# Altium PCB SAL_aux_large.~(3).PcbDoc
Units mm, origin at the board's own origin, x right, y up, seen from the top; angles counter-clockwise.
Board outline 62 x 80 mm, 2 copper layers (Top Layer, Bottom Layer); 29 components, 48 nets, 142 pads, 0 vias.
Unrouted connection lines stored in the file: 78.
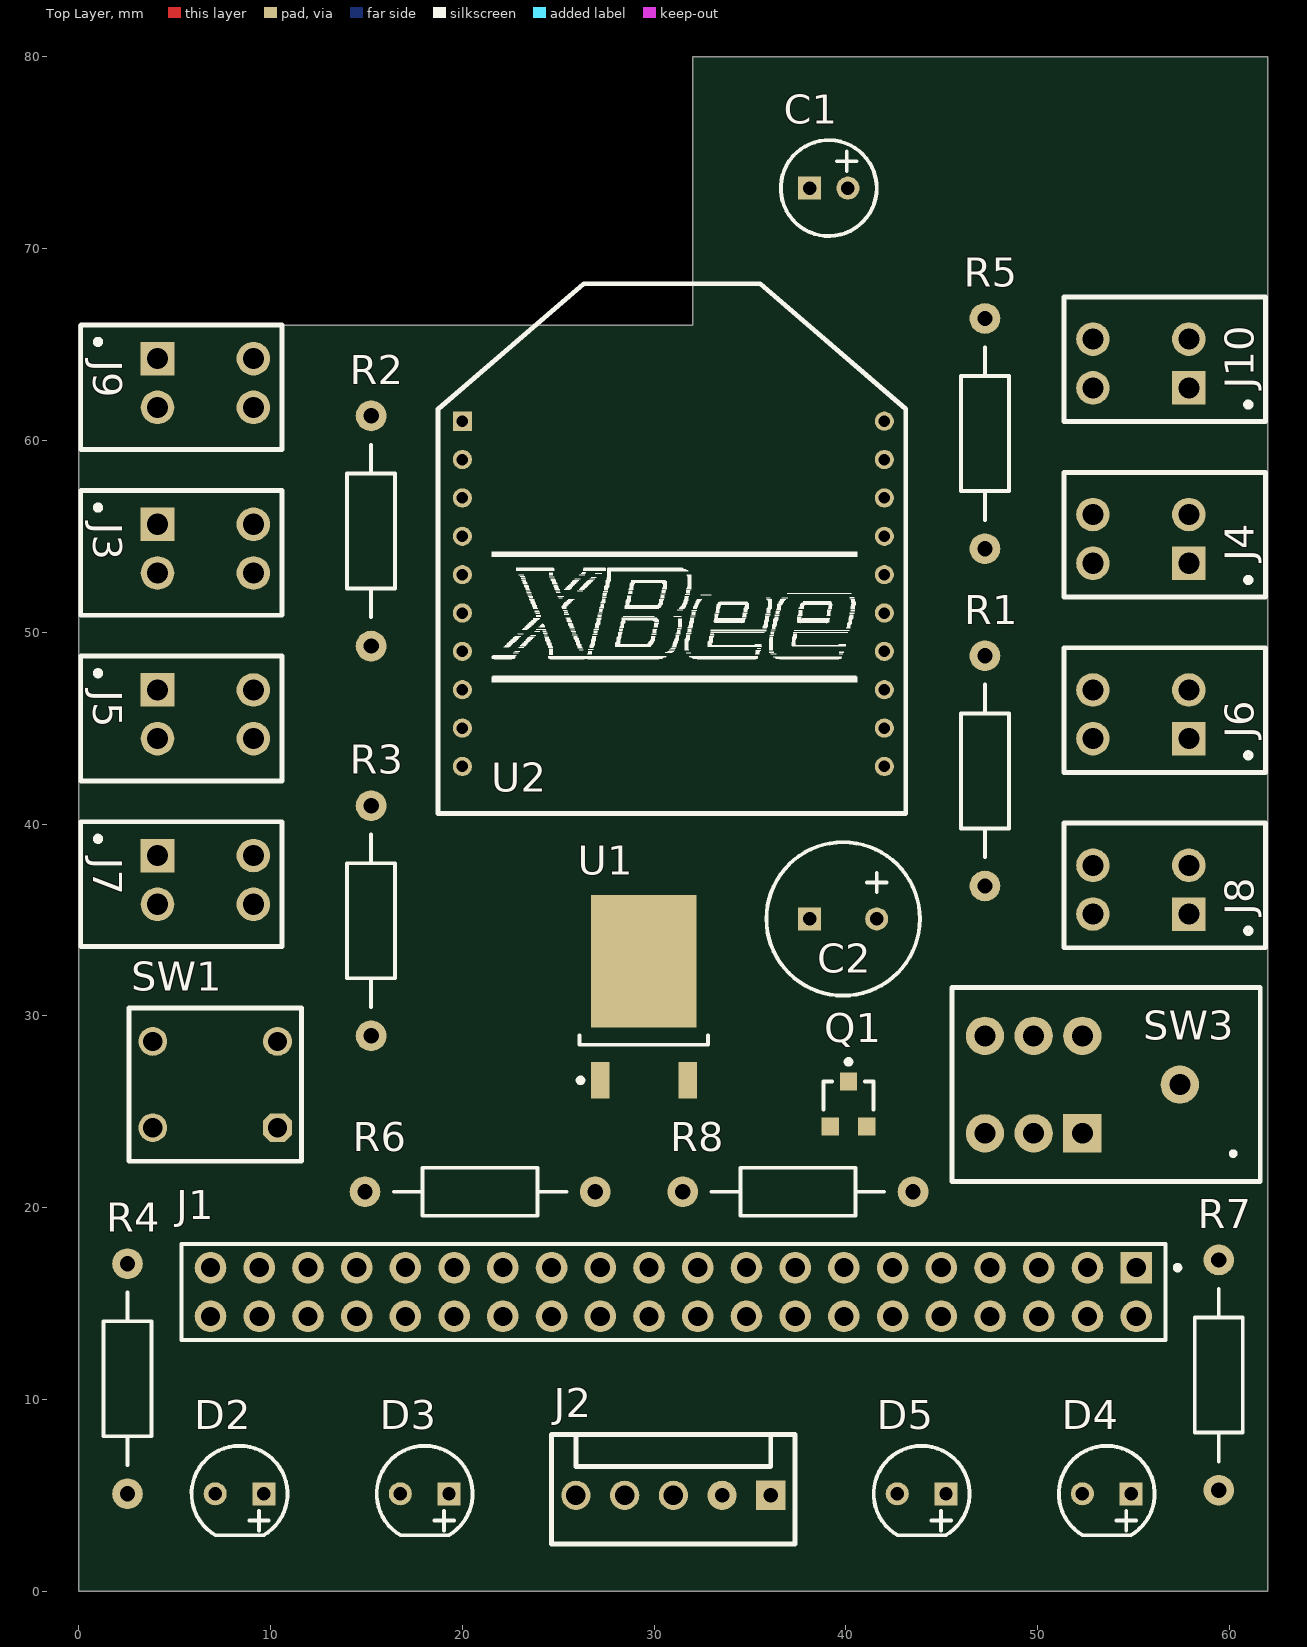
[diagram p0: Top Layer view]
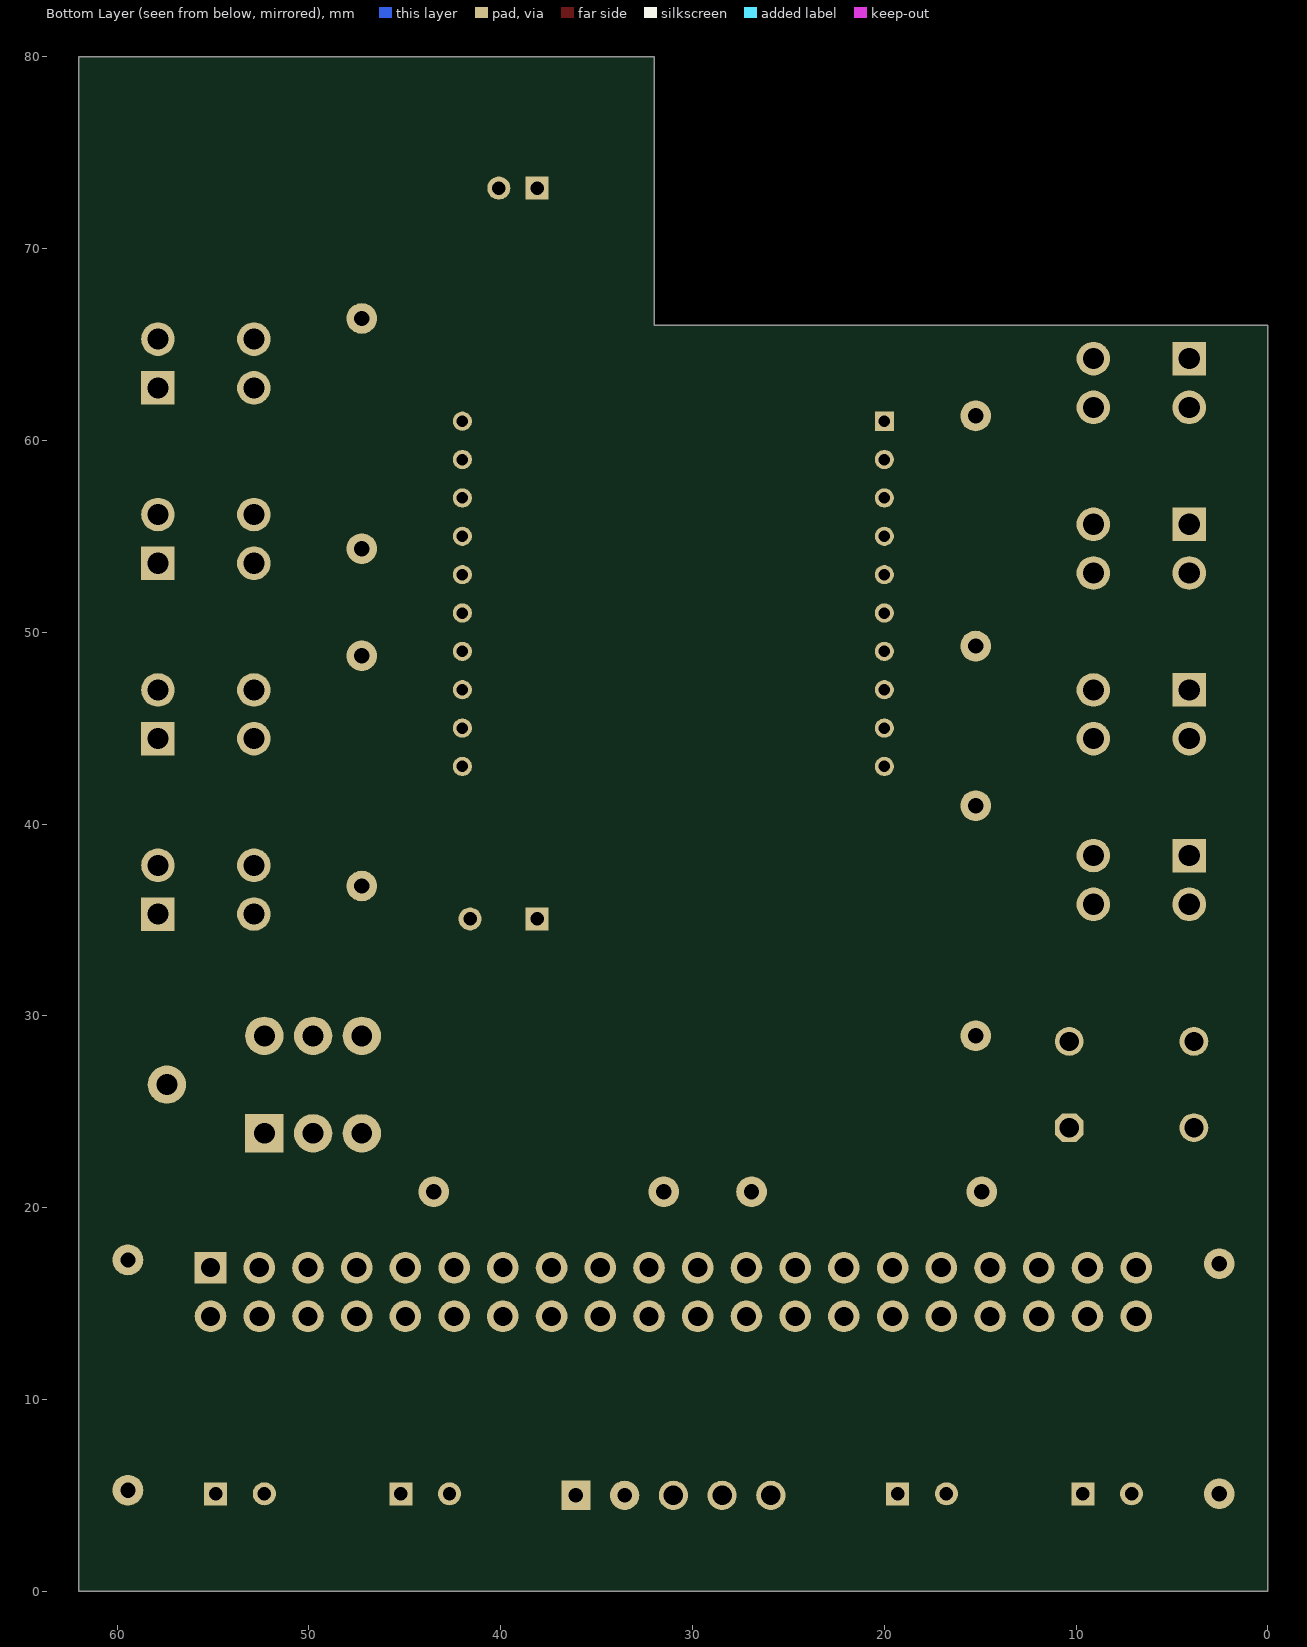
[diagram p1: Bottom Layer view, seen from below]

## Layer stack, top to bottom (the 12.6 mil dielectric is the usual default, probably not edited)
Top Layer: signal copper 0.0356
Dielectric: dielectric 0.32, FR-4, Dk 4.8
Bottom Layer: signal copper 0.0356

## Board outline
0,0 62,0 62,80 32,80 32,66 0,66

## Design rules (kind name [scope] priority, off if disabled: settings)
Clearance [All] p1: gap=0.254
PolygonConnect [All] p1: connectstyle=Relief reliefconductorwidth=0.254 reliefentries=4 polygonreliefangle="90 Angle"
RoomDefinition SAL_aux [InComponentClass('SAL_aux')] p1: confinementstyle=ConfineIn formatcopy=TRUE lockcomponents=FALSE outline 0,0 62,0 62,80 0,80
RoutingVias [All] p1: holewidth=0.711 width=1.27 viastyle="Through Hole" minholewidth=0.711 minwidth=1.27 maxholewidth=0.711 maxwidth=1.27
SilkscreenOverComponentPads [All] p1: minsilkscreentomaskgap=0.254
SolderMaskExpansion [All] p1: expansion=0.102
TestPointUsage [All] p1: valid=0 allowmultiple=FALSE
Testpoint [All] p1: side=15 testpointundercomponent=TRUE minsize=1.016 maxsize=2.54 preferedsize=1.524 minholesize=0 maxholesize=1.016 preferedholesize=0.813 testpointgrid=0.025 style=1023 order=0123456789
Width [All] p1: maxlimit=0.254 minlimit=0.254 preferedwidth=0.254
23 further rules are at their usual default settings.

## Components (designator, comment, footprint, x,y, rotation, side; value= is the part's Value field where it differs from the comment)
C1 "10 uF" "PANASONIC ECA1HAM100X" 38.1,73.152 r0 top
C2 "100 uF" "PANASONIC ECA1HAM101X" 38.1,35.052 r0 top
D2 "Yellow" "VISHAY TLLR4401" 7.112,5.08 r0 top
D3 "Red" "VISHAY TLLR4401" 16.764,5.08 r0 top
D4 "Green" "VISHAY TLLR4401" 52.324,5.08 r0 top
D5 "Blue" "VISHAY TLLR4401" 42.672,5.08 r0 top
J1 "SSW-120-01-G-D" "SAMTEC SSW-120-1-G-D" 31,15.6 r180 top
J2 "I2C Connector" "TYCO 640456-5" 31,5 r0 top
J3 "WAGO 234-502" "WAGO 234-502" 6.604,54.356 r270 top
J4 "WAGO 234-502" "WAGO 234-502" 55.372,54.864 r90 top
J5 "WAGO 234-502" "WAGO 234-502" 6.604,45.72 r270 top
J6 "WAGO 234-502" "WAGO 234-502" 55.372,45.72 r90 top
J7 "WAGO 234-502" "WAGO 234-502" 6.604,37.084 r270 top
J8 "WAGO 234-502" "WAGO 234-502" 55.372,36.576 r90 top
J9 "WAGO 234-502" "WAGO 234-502" 6.604,62.992 r270 top
J10 "WAGO 234-502" "WAGO 234-502" 55.372,64.008 r90 top
Q1 "BSS138" SOT23 40.132,25.4 r0 top
R1 "10K" Resistência 47.244,48.768 r270 top
R2 "10K" Resistência 15.24,49.276 r90 top
R3 "10K" Resistência 15.24,28.956 r90 top
R4 "10K" Resistência 2.54,5.08 r90 top
R5 "1K" Resistência 47.244,54.356 r90 top
R6 "1K" Resistência 26.924,20.828 r180 top
R7 "1K" Resistência 59.436,17.272 r270 top
R8 "1K" Resistência 31.496,20.828 r0 top
SW1 "OMRON B3F-1002" "OMRON B3F-1002" 7.112,26.416 r0 top
SW3 "MULTICOMP 2AD1T2A2M7RE" "MULTICOMP 2AD1T2A2M7RE" 49.784,26.416 r90 top
U1 "LM1117DT-3.3" TD03B_N 29.464,30.988 r90 top
U2 "XBee" XBee 31,51 r0 top

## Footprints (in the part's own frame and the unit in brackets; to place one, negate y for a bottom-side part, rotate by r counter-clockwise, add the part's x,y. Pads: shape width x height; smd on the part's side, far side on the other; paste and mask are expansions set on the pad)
"MULTICOMP 2AD1T2A2M7RE" [mm] "Switch, DPDT ON-ON"
  rect 2x2 hole 1.09: 1(-2.54,-2.54)
  round 2 hole 1.09: 2(-2.54,0) 3(-2.54,2.54) 4(2.54,-2.54) 5(2.54,0) 6(2.54,2.54) GND(0,-7.62)
  silkscreen extent -5.05,-11.81 5.05,4.25
"OMRON B3F-1002" [mm] "6.0mm Tactil Switch"
  oct 1.5x1.5 hole 1: 1(3.25,-2.25)
  round 1.5 hole 1: 2(-3.25,-2.25) 3(3.25,2.25) 4(-3.25,2.25)
  silkscreen extent -4.5,-4 4.5,4
"PANASONIC ECA1HAM100X" [mm]
  rect 1.2x1.2 hole 0.7: 1(0,0)
  round 1.2 hole 0.7: 2(2,0)
  silkscreen extent -1.5,-2.5 3.5,2.5
"PANASONIC ECA1HAM101X" [mm]
  rect 1.2x1.2 hole 0.7: 1(0,0)
  round 1.2 hole 0.7: 2(3.5,0)
  silkscreen extent -2.25,-4 5.75,4
Resistência [mm]
  round 1.6 hole 0.8: 1(0,0) 2(12,0)
  silkscreen extent 1.5,-1.25 10.5,1.25
"SAMTEC SSW-120-1-G-D" [mm]
  rect 1.65x1.65 / inner round 1.65 / far side rect 1.65x1.65 hole 1 mask+0: 1(-24.13,-1.27)
  round 1.65 hole 1 mask+0: 2(-24.13,1.27) 3(-21.59,-1.27) 4(-21.59,1.27) 5(-19.05,-1.27) 6(-19.05,1.27) 7(-16.51,-1.27) 8(-16.51,1.27) 9(-13.97,-1.27) 10(-13.97,1.27) 11(-11.43,-1.27) 12(-11.43,1.27) 13(-8.89,-1.27) 14(-8.89,1.27) 15(-6.35,-1.27) 16(-6.35,1.27) 17(-3.81,-1.27) 18(-3.81,1.27) 19(-1.27,-1.27) 20(-1.27,1.27) 21(1.27,-1.27) 22(1.27,1.27) 23(3.81,-1.27) 24(3.81,1.27) 25(6.35,-1.27) 26(6.35,1.27) 27(8.89,-1.27) 28(8.89,1.27) 29(11.43,-1.27) 30(11.43,1.27) 31(13.97,-1.27) 32(13.97,1.27) 33(16.51,-1.27) 34(16.51,1.27) 35(19.05,-1.27) 36(19.05,1.27) 37(21.59,-1.27) 38(21.59,1.27) 39(24.13,-1.27) 40(24.13,1.27)
  silkscreen extent -26.41,-2.5 25.65,2.5
SOT23 [mm] "SOT-23; 3 Leads; Body 3.1 x 2.5 mm, inc. leads (LxW max), Alternate Lead Configuration"
  rect 0.9x0.95 smd: 1(0,1.175) 2(0.95,-1.175) 3(-0.95,-1.175)
  silkscreen extent -1.3,-0.3 1.3,2.32
TD03B_N [mm] "D-PAK, 4-Leads, Body 6.1x6.6mm, Pitch 2.29mm, Lead Span 9.7mm, IPC Medium Density"
  rect 1.9x0.95 smd: 1(-4.35,2.28) 3(-4.35,-2.28)
  rect 6.9x5.5 smd: 4(1.85,0)
  silkscreen extent -4.47,-3.35 -2,3.43, body extent -2.5,-3.35 3.7,3.35, height 2.38
"TYCO 640456-5" [mil] "I2C Connector"
  rect 60x60 hole 30: 1(200,0)
  round 60 hole 30: 2(100,0)
  round 60 hole 40.16: 3(0,0) 4(-100,0) 5(-200,0)
  silkscreen extent -250,-100 250,125
"VISHAY TLLR4401" [mm] "3mm LED"
  round 1.2 hole 0.7: 1(0,0)
  rect 1.2x1.2 hole 0.7: 2(2.54,0)
  silkscreen extent -1.23,-2.17 3.77,2.5
"WAGO 234-502" [mm]
  rect 1.75x1.75 hole 1.1: 1(-1.27,-2.5)
  round 1.75 hole 1.1: 2(-1.27,2.5) 3(1.27,-2.5) 4(1.27,2.5)
  silkscreen extent -3.03,-6.5 3.47,4
XBee [mm] "ZigBee device"
  rect 1x1 hole 0.6: 1(-11,10)
  round 1 hole 0.6: 2(-11,8) 3(-11,6) 4(-11,4) 5(-11,2) 6(-11,0) 7(-11,-2) 8(-11,-4) 9(-11,-6) 10(-11,-8) 11(11,-8) 12(11,-6) 13(11,-4) 14(11,-2) 15(11,0) 16(11,2) 17(11,4) 18(11,6) 19(11,8) 20(11,10)
  silkscreen extent -12.26,-10.44 12.12,17.17

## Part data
C1: library part "PANASONIC ECA1HAM100X"
C2: library part "PANASONIC ECA1HAM101X"
D2 D3 D4 D5: library part "VISHAY TLLG4401", "Green LED PCB 3mm"
J1: library part "SAMTEC SSW-120-01-G-D"
J2: library part "TYCO 640456-5"
Q1: "N-Channel Enhancement Mode Vertical DMOS FET"
R1 R2 R3 R4 R5 R6 R7 R8: library part Resistência
SW1: "6.0mm Tact Switch"
U1: "800mA Low-Dropout Linear Regulator"

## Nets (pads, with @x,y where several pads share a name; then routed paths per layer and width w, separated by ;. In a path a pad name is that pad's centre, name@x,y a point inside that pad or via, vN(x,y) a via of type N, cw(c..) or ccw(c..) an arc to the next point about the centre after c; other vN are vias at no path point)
1: D2.1 J3.2 J4.2 J5.2 J6.2 J7.2 J8.2 J9.2 J10.2 R5.2
3.3V: Q1.3 R1.2 R5.1 R6.1 R7.1 SW3.6 U2.1
"3.3V OUT": C2.2 SW3.5 U1.4
/INT: J1.20
/RESET: J1.5 J2.1
A0: J1.7
A4/LSDA: J1.1
A5/LSCL: J1.3
B5: J1.10
C0: J1.25
C1: J1.27
C2: J1.29
C5: J1.35
D0: J1.40 J9.3
D1: J1.38 J10.3
D2: J1.36 J7.3
D3: J1.34 J8.3
D4: J1.32 J5.3
D5: J1.30 J6.3
D6: J1.28 J3.3
D7: J1.26 J4.3
DIN: D3.2 Q1.2 R1.1 U2.3
DOUT: D2.2 R3.2 R4.1 U2.2
EYEB: J1.19
EYEF: J1.9
EYEL: J1.13
EYER: J1.11
NetD3_1: D3.1 R6.2
NetD4_1: D4.1 R7.2
NetD5_1: D5.1 R8.2
PWM1/SERVOR: J1.18
PWM2/SERVOL: J1.16
PWM3: J1.14
PWM4: J1.12
RESET: SW1.1 SW1.2 U2.5
RSSI: R8.1 U2.6
RX: J1.39 R4.2
SCL: J1.31
SDA: J1.33
TX: J1.37 Q1.1 R2.1
US_B: J1.17
US_F: J1.15
V+: J1.4
VDD: J1.21 J1.22 J2.2 J3.1 J4.1 J5.1 J6.1 J7.1 J8.1 J9.1 J10.1 SW3.2
"VDD OUT": C1.2 J3.4 J4.4 J5.4 J6.4 J7.4 J8.4 J9.4 J10.4 R2.2 SW3.3 U1.3
VSS: C1.1 C2.1 D4.2 D5.2 J1.2 J1.23 J1.24 J2.3 R3.1 SW1.3 SW1.4 SW3.GND U1.1 U2.10
XAXIS: J1.8 J2.5
YAXIS: J1.6 J2.4
pads on no net: SW3.1 SW3.4 U2.4 U2.7 U2.8 U2.9 U2.11 U2.12 U2.13 U2.14 U2.15 U2.16 U2.17 U2.18 U2.19 U2.20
